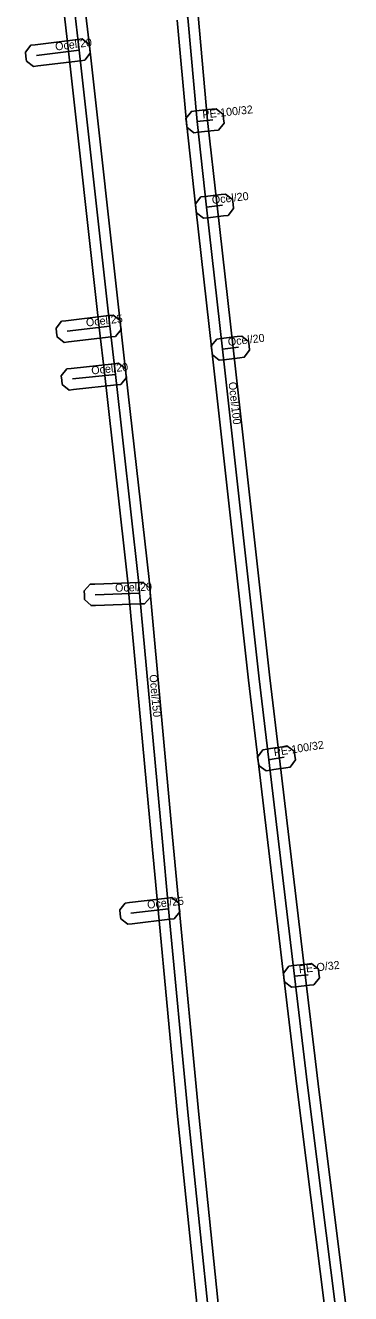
# Model space of a CAD drawing. Extents: x -569373 to -565022, y -1135090 to -1131496.
# Drawn here: x -565661.6 to -565631.1, y -1133454.8 to -1133335.9 of the extents above; entities that cross this region are included whole.
import ezdxf

# ---------------------------------------------------------------- set-up
doc = ezdxf.new("R2010")
doc.units = 0
for name, color, linetype in [('1', 7, 'Continuous'), ('24', 7, 'Continuous'), ('30', 7, 'Continuous')]:
    doc.layers.add(name, color=color, linetype=linetype)

msp = doc.modelspace()

# ---------------------------------------------------------------- linework, layer by layer
at = {"layer": '1'}
for points in [[(-565644.275, -1133468.103), (-565647.365, -1133438.158), (-565649.186, -1133418.783), (-565649.806, -1133412.172), (-565651.906, -1133389.212), (-565652.015, -1133388.042), (-565654.174, -1133368.722), (-565654.684, -1133364.212), (-565657.574, -1133338.331), (-565657.941, -1133335.039)], [(-565655.939, -1133334.941), (-565655.586, -1133338.109), (-565652.696, -1133363.988), (-565652.186, -1133368.498), (-565650.025, -1133387.838), (-565649.914, -1133389.028), (-565647.814, -1133411.988), (-565647.194, -1133418.597), (-565645.375, -1133437.962), (-565642.285, -1133467.897)], [(-565633.122, -1133459.615), (-565636.173, -1133435.341), (-565637.385, -1133425.133), (-565639.794, -1133404.838), (-565640.693, -1133397.264), (-565644.144, -1133366.351), (-565645.634, -1133353.041), (-565646.525, -1133345.02), (-565647.384, -1133335.429)], [(-565645.416, -1133334.971), (-565644.535, -1133344.82), (-565643.646, -1133352.819), (-565642.156, -1133366.129), (-565638.707, -1133397.036), (-565637.808, -1133404.602), (-565635.399, -1133424.897), (-565634.187, -1133435.099), (-565631.138, -1133459.365)]]:
    msp.add_lwpolyline(points, dxfattribs=at)
for points in [[(-565656.047, -1133339.162), (-565656.458, -1133339.213), (-565660.448, -1133339.703), (-565660.859, -1133339.753), (-565661.512, -1133339.243), (-565661.563, -1133338.832), (-565661.613, -1133338.421), (-565661.103, -1133337.768), (-565660.692, -1133337.717), (-565656.702, -1133337.227), (-565656.291, -1133337.177), (-565655.638, -1133337.687), (-565655.587, -1133338.098), (-565655.537, -1133338.509)], [(-565643.521, -1133345.71), (-565643.933, -1133345.754), (-565645.423, -1133345.914), (-565645.835, -1133345.958), (-565646.48, -1133345.439), (-565646.524, -1133345.027), (-565646.568, -1133344.615), (-565646.049, -1133343.97), (-565645.637, -1133343.926), (-565644.147, -1133343.766), (-565643.735, -1133343.722), (-565643.09, -1133344.241), (-565643.046, -1133344.653), (-565643.002, -1133345.065)], [(-565645.165, -1133351.983), (-565644.753, -1133351.936), (-565643.263, -1133351.766), (-565642.852, -1133351.719), (-565642.203, -1133352.235), (-565642.156, -1133352.647), (-565642.109, -1133353.058), (-565642.625, -1133353.707), (-565643.037, -1133353.754), (-565644.527, -1133353.924), (-565644.938, -1133353.971), (-565645.587, -1133353.455), (-565645.634, -1133353.043), (-565645.681, -1133352.632)], [(-565653.162, -1133365.045), (-565653.573, -1133365.093), (-565657.573, -1133365.563), (-565657.984, -1133365.611), (-565658.635, -1133365.098), (-565658.683, -1133364.687), (-565658.731, -1133364.276), (-565658.218, -1133363.625), (-565657.807, -1133363.577), (-565653.807, -1133363.107), (-565653.396, -1133363.059), (-565652.745, -1133363.572), (-565652.697, -1133363.983), (-565652.649, -1133364.394)], [(-565643.679, -1133365.296), (-565643.268, -1133365.247), (-565641.758, -1133365.067), (-565641.347, -1133365.018), (-565640.696, -1133365.531), (-565640.647, -1133365.942), (-565640.598, -1133366.353), (-565641.111, -1133367.004), (-565641.522, -1133367.053), (-565643.032, -1133367.233), (-565643.443, -1133367.282), (-565644.094, -1133366.769), (-565644.143, -1133366.358), (-565644.192, -1133365.947)], [(-565652.662, -1133369.56), (-565653.074, -1133369.604), (-565657.104, -1133370.034), (-565657.516, -1133370.078), (-565658.16, -1133369.558), (-565658.204, -1133369.146), (-565658.248, -1133368.734), (-565657.728, -1133368.09), (-565657.316, -1133368.046), (-565653.286, -1133367.616), (-565652.874, -1133367.572), (-565652.23, -1133368.092), (-565652.186, -1133368.504), (-565652.142, -1133368.916)], [(-565650.46, -1133390.104), (-565650.874, -1133390.119), (-565655.044, -1133390.269), (-565655.458, -1133390.284), (-565656.064, -1133389.72), (-565656.079, -1133389.306), (-565656.094, -1133388.892), (-565655.53, -1133388.286), (-565655.116, -1133388.271), (-565650.946, -1133388.121), (-565650.532, -1133388.106), (-565649.926, -1133388.67), (-565649.911, -1133389.084), (-565649.896, -1133389.498)], [(-565639.373, -1133403.802), (-565638.965, -1133403.734), (-565638.66, -1133403.683), (-565637.516, -1133403.502), (-565637.107, -1133403.437), (-565636.437, -1133403.925), (-565636.372, -1133404.334), (-565636.307, -1133404.743), (-565636.795, -1133405.413), (-565637.204, -1133405.478), (-565638.34, -1133405.657), (-565638.637, -1133405.706), (-565639.046, -1133405.774), (-565639.719, -1133405.292), (-565639.787, -1133404.884), (-565639.855, -1133404.475)], [(-565647.664, -1133419.635), (-565648.075, -1133419.683), (-565651.615, -1133420.093), (-565652.026, -1133420.141), (-565652.675, -1133419.626), (-565652.723, -1133419.215), (-565652.771, -1133418.804), (-565652.256, -1133418.155), (-565651.845, -1133418.107), (-565648.305, -1133417.697), (-565647.894, -1133417.649), (-565647.245, -1133418.164), (-565647.197, -1133418.575), (-565647.149, -1133418.986)], [(-565634.586, -1133425.817), (-565634.998, -1133425.864), (-565636.28, -1133426.009), (-565636.691, -1133426.055), (-565637.339, -1133425.539), (-565637.386, -1133425.127), (-565637.432, -1133424.716), (-565636.916, -1133424.068), (-565636.504, -1133424.021), (-565635.222, -1133423.876), (-565634.811, -1133423.83), (-565634.163, -1133424.346), (-565634.116, -1133424.758), (-565634.07, -1133425.169)]]:
    msp.add_lwpolyline(points, close=True, dxfattribs=at)
at = {"layer": '24'}
for points in [[(-565632.13, -1133459.49), (-565635.18, -1133435.22), (-565636.392, -1133425.015), (-565638.801, -1133404.72), (-565639.7, -1133397.15), (-565643.15, -1133366.24), (-565644.64, -1133352.93), (-565645.53, -1133344.92), (-565646.4, -1133335.2), (-565648.67, -1133329.3), (-565648.67, -1133329.27), (-565652.07, -1133297.74), (-565652.7, -1133293.42), (-565653.46, -1133288.28), (-565652.15, -1133285.62), (-565652.17, -1133280.3)], [(-565656.82, -1133325.86), (-565656.92, -1133333.37), (-565656.94, -1133334.99), (-565656.58, -1133338.22), (-565653.69, -1133364.1), (-565653.18, -1133368.61), (-565651.02, -1133387.94), (-565650.91, -1133389.12), (-565648.81, -1133412.08), (-565648.19, -1133418.69), (-565646.37, -1133438.06), (-565643.28, -1133468)], [(-565656.58, -1133338.22), (-565660.57, -1133338.71)], [(-565644.04, -1133344.76), (-565645.53, -1133344.92)], [(-565644.64, -1133352.93), (-565643.15, -1133352.76)], [(-565653.69, -1133364.1), (-565657.69, -1133364.57)], [(-565643.15, -1133366.24), (-565641.64, -1133366.06)], [(-565653.18, -1133368.61), (-565657.21, -1133369.04)], [(-565650.91, -1133389.12), (-565655.08, -1133389.27)], [(-565638.801, -1133404.72), (-565638.5, -1133404.67), (-565637.36, -1133404.49)], [(-565648.19, -1133418.69), (-565651.73, -1133419.1)], [(-565635.11, -1133424.87), (-565636.392, -1133425.015)]]:
    msp.add_lwpolyline(points, dxfattribs=at)

# ---------------------------------------------------------------- texts
at = {"layer": '30'}
for s, rotation, p in [('Ocel/20', 7.00127, (-565658.775, -1133338.265)), ('PE-100/32', 6.12908, (-565644.985, -1133344.64)), ('Ocel/20', 6.50896, (-565644.095, -1133352.645)), ('Ocel/25', 6.70153, (-565655.89, -1133364.135)), ('Ocel/20', 6.79788, (-565642.595, -1133365.95)), ('Ocel/20', 6.0904, (-565655.395, -1133368.625)), ('Ocel/100', 276.36867, (-565642.58, -1133369.358)), ('Ocel/20', 2.06011, (-565653.195, -1133388.995)), ('Ocel/150', 275.22593, (-565649.993, -1133396.764)), ('PE-100/32', 8.97263, (-565638.281, -1133404.404)), ('Ocel/25', 6.60652, (-565650.16, -1133418.695)), ('PE-O/32', 6.45299, (-565635.951, -1133424.743))]:
    msp.add_text(s, height=0.75, rotation=rotation, dxfattribs=at).set_placement(p)

doc.saveas('drawing.dxf')
